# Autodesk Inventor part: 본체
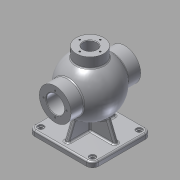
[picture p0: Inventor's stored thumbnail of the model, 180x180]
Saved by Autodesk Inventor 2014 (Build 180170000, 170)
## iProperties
Created: 2015-10
Part Number: 본체
Material: Aluminum 6061
Document SubType Name: Modeling
Designer: youjin10
Density: 2.71 g/cm^3
Appearance: Aluminum - Flat
Mass: 1509.57 g
Surface Area: 1153.7 cm^2
Volume: 557.037 cm^3
Author: youjin10
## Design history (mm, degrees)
sketch "Sketch1"
  geometry: L1 (62.5, -57.5)-(-62.5, -57.5); L2 (-62.5, -57.5)-(-62.5, 57.5); L3 (-62.5, 57.5)-(62.5, 57.5); L4 (62.5, 57.5)-(62.5, -57.5); L5 (62.5, -57.5)-(-62.5, 57.5); L6 (-62.5, -57.5)-(62.5, 57.5); 1 further point
  constraints: 12 end point, 2 midpoint, 2 parallel, 1 horizontal, 1 perpendicular
  dimensions: "d0" = 125 distance of L2.end L3.end; "d1" = 115 distance of L1.end L2.end
extrude "Extrusion1" new body sketch "Sketch1" distance "d2" = 10; taper "d3" = 0 deg
workplane "Work Plane1"
sketch "Sketch4"
  geometry: L1 (0, 53)-(0, -53); L2 (8.646, -43.503)-(8.646, 43.503); A1 r 53 centre (0, 0) between (0, -53) and (0, 53); A2 r 44.354 centre (0, 0) between (8.646, -43.503) and (8.646, 43.503); 2 further points
  constraints: 4 end point, 4 point on circle, 2 centre point, 1 coincident, 1 midpoint, 1 vertical, 1 other
  dimensions: "d9" = 106 distance of L1.start L1.end; "d10" = 53 radius of A1
revolve "Revolution1" stored, may be unused: angle "d11" = 180 deg
workplane "Work Plane2"
sketch "Sketch6"
  geometry: C1 r 31 at (0, 85); 1 further point
  constraints: 1 centre point, 1 vertical alignment
  dimensions: "d13" = 62 diameter of C1; "d14" = 85 distance of point (0, 0) C1.centre
extrude "Extrusion2" join sketch "Sketch6" stored distance "d15" = 10; taper "d16" = 0 deg
mirror "Mirror1"
sketch "Sketch9"
  geometry: C1 r 31 at (0, 0) reference; C2 r 17.5 at (0, 0); 1 further point
  constraints: 1 centre point, 1 coincident
  dimensions: "d20" = 35 diameter of C2
extrude "Extrusion3" cut sketch "Sketch9" distance "d21" = 16; taper "d22" = 0 deg
sketch "Sketch10"
  geometry: C1 r 17.5 at (0, 0) reference; C2 r 18.5 at (0, 0); 1 further point
  constraints: 1 centre point, 1 coincident
  dimensions: "d23" = 37 diameter of C2
extrude "Extrusion4" cut sketch "Sketch10" distance "d24" = 1.75; taper "d25" = 0 deg
sketch "Sketch11"
  geometry: C1 r 18.5 at (0, 0) reference; C2 r 17.5 at (0, 0); 1 further point
  constraints: 1 centre point, 1 coincident
  dimensions: "d26" = 35 diameter of C2
extrude "Extrusion5" cut sketch "Sketch11" stored distance "d27" = 1.75; taper "d28" = 0 deg
workplane "Work Plane3"
sketch "Sketch12"
  geometry: C1 r 27 at (0, 0); 1 further point
  constraints: 1 centre point, 1 coincident
  dimensions: "d30" = 54 diameter of C1
extrude "Extrusion6" join sketch "Sketch12" stored distance "d31" = 1.75; taper "d32" = 0 deg
sketch "Sketch13"
  geometry: C1 r 27 at (0, 0) reference; C2 r 13 at (0, 0)
  constraints: 1 centre point, 1 coincident
  dimensions: "d33" = 26 diameter of C2
extrude "Extrusion7" cut sketch "Sketch13" distance "d34" = 50; taper "d35" = 0 deg
sketch "Sketch14"
  geometry: C1 r 17.5 at (0, 0) reference; C2 r 31 at (0, 0) reference; A1 r 22.5 centre (0, 0) between (0, 22.5) and (-22.5, 0); 3 further points
  constraints: 4 point on circle, 2 horizontal alignment, 2 vertical alignment, 1 centre point, 1 coincident
  dimensions: "d36" = 45 diameter of A1
hole "Hole1" sketch "Sketch14" at (0, 22.5), (-22.5, 0), (0, -22.5), (22.5, 0) diameter "d37" = 3.242; stored, may be unused: countersink angle "d41" = 90 deg, drill point angle "d43" = 118 deg; dims "d38" = 12, "d39" = 4, "d40" = 2, "d42" = 15
sketch "Sketch15"
  geometry: C1 r 17.5 at (0, 0) reference; C2 r 31 at (0, 0) reference; A1 r 24 centre (0, 0) between (0, 24) and (-24, 0); 3 further points
  constraints: 4 point on circle, 2 horizontal alignment, 2 vertical alignment, 1 centre point, 1 coincident
  dimensions: "d44" = 48 diameter of A1
hole "Hole2" sketch "Sketch15" at (0, 24), (-24, 0), (0, -24), (24, 0) diameter "d45" = 3.242; stored, may be unused: countersink angle "d49" = 90 deg, drill point angle "d51" = 118 deg; dims "d46" = 16, "d47" = 4, "d48" = 2, "d50" = 19
sketch "Sketch16"
  geometry: C1 r 13 at (0, 0) reference; C2 r 27 at (0, 0) reference; A1 r 20 centre (0, 0) between (0, 20) and (-20, 0); 2 further points
  constraints: 4 point on circle, 2 horizontal alignment, 2 vertical alignment, 1 centre point, 1 coincident
  dimensions: "d52" = 40 diameter of A1
hole "Hole3" sketch "Sketch16" at (0, 20), (-20, 0), (0, -20), (20, 0) diameter "d53" = 3.242; stored, may be unused: countersink angle "d57" = 90 deg, drill point angle "d59" = 118 deg; dims "d54" = 9, "d55" = 4, "d56" = 2, "d58" = 11
sketch "Sketch17"
  geometry: L1 (4, -4)-(-4, -4); L2 (-4, -4)-(-4, 4); L3 (-4, 4)-(4, 4); L4 (4, 4)-(4, -4); L5 (4, -4)-(-4, 4); L6 (-4, -4)-(4, 4); 1 further point
  constraints: 12 end point, 2 midpoint, 2 parallel, 1 horizontal, 1 perpendicular
  dimensions: "d60" = 8 distance of L2.end L3.end; "d61" = 8 distance of L1.end L2.end
extrude "Extrusion8" join sketch "Sketch17" stored distance "d62" = 50; taper "d63" = 0 deg
workplane "Work Plane4"
workplane "Work Plane5"
sketch "Sketch19"
  geometry: L1 (0, 43)-(0, -43); A1 r 43 centre (0, 0) between (0, -43) and (0, 43); 2 further points
  constraints: 2 end point, 2 point on circle, 1 centre point, 1 coincident, 1 midpoint, 1 vertical
  dimensions: "d66" = 86 distance of L1.start L1.end; "d67" = 43 radius of A1
revolve "Revolution3" sketch "Sketch19" stored, may be unused: angle "d68" = 180 deg
workplane "Work Plane6"
sketch "Sketch20"
  geometry: L1 (62.5, 10)-(-62.5, 10) reference; L2 (-37.379, 47.426)-(-52.5, 10); L3 (-62.5, 0)-(-62.5, 10) reference; L4 (37.379, 47.426)-(52.5, 10); L5 (62.5, 0)-(62.5, 10) reference; A1 r 53 centre (0, 85) between (-27, 130.607) and (27, 130.607) reference; 1 further point
  constraints: 4 end point, 2 point on circle, 2 point on line
  dimensions: "d70" = 10 distance from line of L2.end L3; "d71" = 22 deg angle of L2 L3; "d78" = 10 distance from line of L5 L4.end; "d79" = 22 deg angle of L5 L4
feature "Rib1" dims "d72" = 1, "d73" = 8, "d74" = 0, "d75" = 0, "d76" = 1, "d77" = 1
feature "Rib2" dims "d80" = 1, "d81" = 8, "d82" = 0, "d83" = 0, "d84" = 1, "d85" = 1
sketch "Sketch21"
  geometry: L1 (-52.026, 107.5)-(-53, 109.121) reference; L2 (-53, 109.121)-(-68, 109.121) reference; L3 (-68, 109.121)-(-68, 116) reference; L4 (-68, 116)-(-42.988, 116) reference; L5 (-27, 130.607)-(-27, 150) reference; L6 (-27, 150)-(-21.621, 150) reference; L7 (-21.621, 150)-(-21.621, 139) reference; L8 (-21.621, 139)-(-20, 138.026) reference; L9 (-20, 138.026)-(-18.379, 139) reference; L10 (-18.379, 139)-(-18.379, 150) reference; L11 (-18.379, 150)-(-13, 150) reference; L12 (-13, 150)-(-13, 125.988) reference; L13 (-39.278, 102.5)-(-68, 102.5) reference; L14 (-68, 102.5)-(-68, 105.879) reference; L15 (-68, 105.879)-(-53, 105.879) reference; L16 (-53, 105.879)-(-52.026, 107.5) reference; L17 (50.25, 66.5)-(52, 66.5) reference; L18 (52, 66.5)-(52, 67.5) reference; L19 (52, 67.5)-(68, 67.5) reference; L20 (68, 67.5)-(68, 62.621) reference; L21 (68, 62.621)-(49, 62.621) reference; L22 (49, 62.621)-(48.026, 61) reference; L23 (48.026, 61)-(49, 59.379) reference; L24 (49, 59.379)-(68, 59.379) reference; L25 (68, 59.379)-(68, 54) reference; L26 (68, 54)-(42.988, 54) reference; L27 (4, 32.151)-(4, 10) reference; L28 (4, 10)-(57.5, 10) reference; L29 (57.5, 10)-(57.5, 0) reference; L30 (57.5, 0)-(-57.5, 0) reference; L31 (-57.5, 0)-(-57.5, 10) reference; L32 (-57.5, 10)-(-4, 10) reference; L33 (-4, 10)-(-4, 32.151) reference; L34 (-42.988, 54)-(-68, 54) reference; L35 (-68, 54)-(-68, 60.879) reference; L36 (-68, 60.879)-(-53, 60.879) reference; L37 (-53, 60.879)-(-52.026, 62.5) reference; L38 (-52.026, 62.5)-(-53, 64.121) reference; L39 (-53, 64.121)-(-68, 64.121) reference; L40 (-68, 64.121)-(-68, 67.5) reference; L41 (-68, 67.5)-(-39.278, 67.5) reference; L42 (39.278, 67.5)-(50.25, 67.5) reference; L43 (50.25, 67.5)-(50.25, 66.5) reference; L44 (52, 103.5)-(50.25, 103.5) reference; L45 (50.25, 103.5)-(50.25, 102.5) reference; L46 (50.25, 102.5)-(39.278, 102.5) reference; L47 (13, 125.988)-(13, 150) reference; L48 (13, 150)-(18.379, 150) reference; L49 (18.379, 150)-(18.379, 139) reference; L50 (18.379, 139)-(20, 138.026) reference; L51 (20, 138.026)-(21.621, 139) reference; L52 (21.621, 139)-(21.621, 150) reference; L53 (21.621, 150)-(27, 150) reference; L54 (27, 150)-(27, 130.607) reference; L55 (42.988, 116)-(68, 116) reference; L56 (68, 116)-(68, 110.621) reference; L57 (68, 110.621)-(49, 110.621) reference; L58 (49, 110.621)-(48.026, 109) reference; L59 (48.026, 109)-(49, 107.379) reference; L60 (49, 107.379)-(68, 107.379) reference; L61 (68, 107.379)-(68, 102.5) reference; L62 (68, 102.5)-(52, 102.5) reference; L63 (52, 102.5)-(52, 103.5) reference; L64 (-33.719, 44.109)-(-47.5, 10)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; A1 r 53 centre (0, 85) between (-27, 130.607) and (-42.988, 116) reference; A2 r 43 centre (0, 85) between (-13, 125.988) and (-39.278, 102.5) reference; A3 r 53 centre (0, 85) between (4, 32.151) and (42.988, 54) reference; A4 r 53 centre (0, 85) between (-42.988, 54) and (-4, 32.151) reference; A5 r 43 centre (0, 85) between (-39.278, 67.5) and (0, 42) reference; A6 r 43 centre (0, 85) between (0, 42) and (39.278, 67.5) reference; A7 r 43 centre (0, 85) between (39.278, 102.5) and (13, 125.988) reference; A8 r 53 centre (0, 85) between (42.988, 116) and (27, 130.607) reference; 1 further point
  constraints: 4 end point, 2 point on circle, 2 point on line
  dimensions: "d87" = 22 deg angle of L31 L64; "d88" = 10 distance from line of L31 L64.end; "d89" = 22 deg angle of L29 L65; "d90" = 10 distance from line of L29 L65.end
  node "Project Cut Edges1"
feature "Rib3" dims "d91" = 1, "d92" = 8, "d93" = 0, "d94" = 0, "d95" = 1, "d96" = 1
feature "Rib4" dims "d97" = 1, "d98" = 8, "d99" = 0, "d100" = 0, "d101" = 1, "d102" = 1
workplane "Work Plane7"
sketch "Sketch23"
  geometry: L1 (-42.988, 69.768)-(-68, 69.768) reference; L2 (-68, 69.768)-(-68, 100.232) reference; L3 (-68, 100.232)-(-42.988, 100.232) reference; L4 (0, 150)-(0, 130.607) reference; L5 (-4, 10)-(-4, 39.569) reference; L6 (-57.5, 10)-(-4, 10) reference; L7 (-57.5, 0)-(-57.5, 10) reference; L8 (57.5, 0)-(-57.5, 0) reference; L9 (57.5, 10)-(57.5, 0) reference; L10 (4, 10)-(57.5, 10) reference; L11 (4, 39.569)-(4, 10) reference; L12 (68, 69.768)-(42.988, 69.768) reference; L13 (68, 100.232)-(68, 69.768) reference; L14 (42.988, 100.232)-(68, 100.232) reference; L15 (-27, 150)-(27, 150) reference; L16 (-27, 150)-(-27, 130.607) reference; C1 r 33.466 at (0, 85) reference; A1 r 45.607 centre (0, 85) between (-42.988, 69.768) and (-4, 39.569) reference; A2 r 45.607 centre (0, 85) between (42.988, 100.232) and (0, 130.607) reference; A3 r 45.607 centre (0, 85) between (4, 39.569) and (42.988, 69.768) reference; A4 r 45.607 centre (0, 85) between (0, 130.607) and (-42.988, 100.232) reference; 2 further points
  constraints: 1 vertical alignment, 1 other
  dimensions: "d104" = 10 distance from line of point (0, 140) L15
emboss "Emboss1" sketch "Sketch23" dims "d105" = 0.5, "d106" = 0
sketch "Sketch24"
  geometry: 5 further points
  constraints: 2 horizontal alignment, 2 vertical alignment
  dimensions: "d110" = 45.5 vertical distance of point (0, 0) point (50.5, -45.5); "d111" = 45.5 vertical distance of point (0, 0) point (50.5, 45.5); "d112" = 50.5 horizontal distance of point (0, 0) point (50.5, -45.5); "d113" = 50.5 horizontal distance of point (0, 0) point (-50.5, -45.5)
hole "Hole4" sketch "Sketch24" at (-50.5, 45.5), (50.5, 45.5), (-50.5, -45.5), (50.5, -45.5) diameter "d114" = 8; stored, may be unused: countersink angle "d118" = 90 deg, drill point angle "d120" = 118 deg; dims "d115" = 6, "d116" = 12, "d117" = 3, "d119" = 8
chamfer "Chamfer1" distance "d121" = 1; stored, may be unused: second distance "d122" = 2, angle "d123" = 45 deg
fillet "Fillet1" dims "d124" = 12
fillet "Fillet2" dims "d125" = 3
fillet "Fillet3" dims "d126" = 3
fillet "Fillet4" dims "d127" = 3
body "Solid1"
node "Project Cut Edges2"
other parameters: "d8" = 85, "d12" = -68, "d64" = 0, "d65" = 85, "d69" = 0, "d103" = -27
